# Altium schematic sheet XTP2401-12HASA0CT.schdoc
size 127 x 101 mm
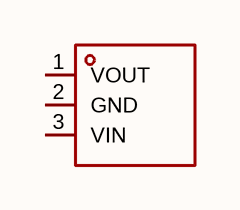
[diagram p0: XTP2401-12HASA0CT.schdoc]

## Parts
U?  xtp2401-12hasa0ct  [SOT-89-3_L4.5-W2.5-P1.50-LS4.2-TL]  (value not drawn)

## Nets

Not connected (* = marked no-connect by the designer): U? 1(VOUT) 2(GND) 3(VIN)

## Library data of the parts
U? = xtp2401-12hasa0ct: 输出极性:正极;工作电压:40V;输出电压:12V;输出电流:150mA;电源纹波抑制比(PSRR):45dB@(1kHz);输出类型:固定;; Manufacturer: XTX(芯天下); AddInBom: yes; ModelId: c8ce1a1e9e8c456c92ba452c2c7c247d; ModelTransform: 161.417,169.291,0,0,0,0,18.622,0,0; Output Configuration: 正极; Voltage - Supply: 40V; Output Voltage: 12V; Output Current: 150mA; Voltage Dropout: 650mV@(150mA); standby current: 6uA; Output Type: 固定; Number of Outputs: 1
